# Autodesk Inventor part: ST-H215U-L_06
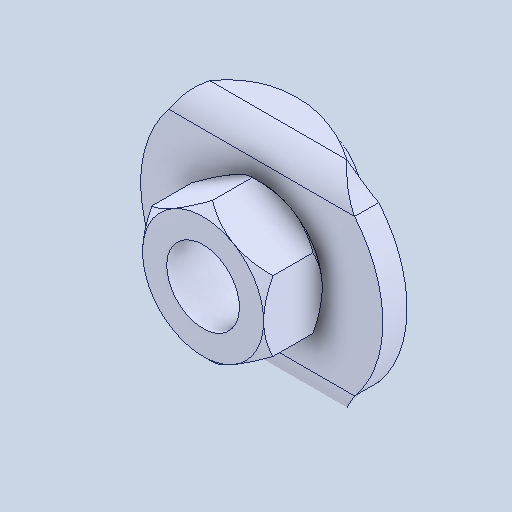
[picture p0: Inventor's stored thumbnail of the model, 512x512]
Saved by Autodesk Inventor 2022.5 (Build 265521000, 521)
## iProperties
Created: 2024-07
Part Number: ST-H215U-L_06
Material: 一般
Document SubType Name: Modeling
Designer: ImaoCorp
Density: 1 g/cm^3
Appearance: 既定
Author: ImaoCorp
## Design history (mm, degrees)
feature "ST-H215U-L_06"
node "ソリッド1"
